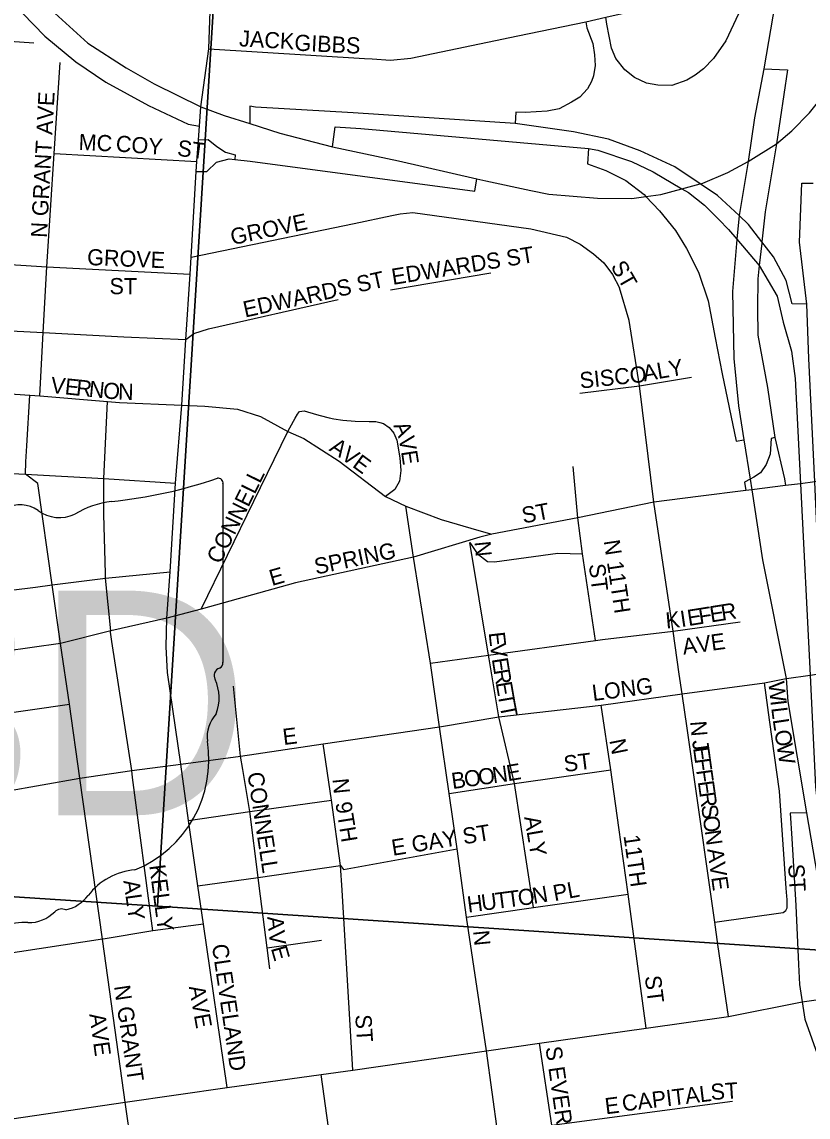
# Model space of a CAD drawing. Extents: x 0 to 34, y -6.2 to 22.
# Drawn here: x 7.114 to 7.576, y 18.119 to 18.762 of the extents above; entities that cross this region are included whole.
import ezdxf

# ---------------------------------------------------------------- set-up
doc = ezdxf.new("R2010")
doc.units = 0
for name, color, linetype in [('GM_X_City_Street', 7, 'Continuous'), ('GM_X_City_Street_Text', 7, 'Continuous'), ('GM_X_Interchange_Ramps', 7, 'Continuous'), ('GM_X_Interstate_Route', 7, 'Continuous'), ('GM_X_Section', 7, 'Continuous'), ('GM_X_State_Route', 7, 'Continuous'), ('GM_X_State_Shield', 7, 'Continuous'), ('GM_X_US_Route', 7, 'Continuous')]:
    doc.layers.add(name, color=color, linetype=linetype)

msp = doc.modelspace()

# ---------------------------------------------------------------- linework, layer by layer
at = {"layer": 'GM_X_City_Street'}
for points in [[(7.40517, 18.7533), (7.44499, 18.76153), (7.45674, 18.76428), (7.47785, 18.76892)], [(7.00564, 18.75627), (7.07288, 18.75262), (7.12097, 18.74924)], [(7.31508, 18.7401), (7.31966, 18.73982), (7.33048, 18.73914), (7.3424, 18.74032), (7.40517, 18.7533)], [(7.22375, 18.74564), (7.31508, 18.7401)], [(7.12443, 18.54206), (7.12656, 18.57921), (7.12864, 18.61789), (7.13299, 18.6844), (7.13639, 18.7378)], [(7.13299, 18.6844), (7.21671, 18.6797)], [(7.21331, 18.62353), (7.30909, 18.64316), (7.33113, 18.64792), (7.33606, 18.64893), (7.34356, 18.64973), (7.41273, 18.6401), (7.43371, 18.6352), (7.44184, 18.63115), (7.44953, 18.62554), (7.45555, 18.62008), (7.46072, 18.61323), (7.46492, 18.60552)], [(7.06414, 18.62187), (7.12864, 18.61789), (7.21273, 18.61353)], [(7.33044, 18.60435), (7.3892, 18.61425)], [(7.49995, 18.3788), (7.49637, 18.40414), (7.48497, 18.47979), (7.47654, 18.54796), (7.47052, 18.58635), (7.46492, 18.60552)], [(7.21027, 18.57512), (7.21498, 18.57874), (7.22358, 18.58147), (7.29973, 18.59872)], [(7.06178, 18.5827), (7.12656, 18.57921), (7.17383, 18.57683), (7.21027, 18.57512)], [(7.44154, 18.54379), (7.47654, 18.54796), (7.50705, 18.55304)], [(7.07551, 18.5454), (7.11865, 18.54255), (7.12443, 18.54206), (7.16429, 18.53873), (7.17125, 18.53815), (7.2078, 18.53656), (7.22144, 18.53599), (7.24054, 18.53434), (7.25401, 18.53006), (7.27006, 18.52113), (7.27946, 18.51702), (7.3002, 18.50376), (7.32739, 18.48315), (7.3394, 18.47731), (7.36009, 18.46962), (7.38216, 18.46319), (7.3898, 18.46097)], [(7.11688, 18.51286), (7.11865, 18.54255)], [(7.16307, 18.43797), (7.16211, 18.47254), (7.16216, 18.49368), (7.16429, 18.53873)], [(7.21924, 18.4169), (7.25019, 18.48025), (7.27006, 18.52113), (7.27345, 18.52733), (7.27434, 18.52897), (7.27585, 18.53145), (7.27703, 18.53288), (7.27968, 18.53336), (7.28699, 18.53111), (7.28908, 18.53056), (7.29447, 18.52914), (7.29711, 18.52873), (7.30237, 18.52792), (7.3097, 18.52719), (7.31792, 18.527), (7.32184, 18.52698), (7.32405, 18.52645), (7.32625, 18.52592), (7.32968, 18.52357), (7.33242, 18.52031), (7.33415, 18.51616), (7.3358, 18.5058), (7.33646, 18.49827), (7.33609, 18.49517), (7.33572, 18.49207), (7.33294, 18.48726), (7.32739, 18.48315)], [(7.17384, 18.13335), (7.16128, 18.22326), (7.1479, 18.31772), (7.14186, 18.36126), (7.13656, 18.39686), (7.13185, 18.43116), (7.1233, 18.49067), (7.11613, 18.49608), (7.11632, 18.50342), (7.11688, 18.51286)], [(6.99821, 18.50104), (7.02122, 18.50104), (7.05393, 18.49933), (7.07201, 18.49838), (7.11613, 18.49608), (7.16216, 18.49368), (7.20423, 18.49087)], [(7.45072, 18.39857), (7.4432, 18.4494), (7.44044, 18.47054), (7.43756, 18.50073)], [(7.58621, 18.49247), (7.57946, 18.49162), (7.57113, 18.49058), (7.56236, 18.48948), (7.54244, 18.48698), (7.5391, 18.48656), (7.51105, 18.48305)], [(7.56292, 18.37635), (7.57672, 18.37829), (7.58468, 18.37941), (7.591, 18.3803), (7.59427, 18.38091), (7.62982, 18.38756), (7.67292, 18.39175), (7.74898, 18.40202), (7.80065, 18.40857), (7.84375, 18.41455), (7.87636, 18.42025), (7.91447, 18.42624), (7.98084, 18.43482), (8.02749, 18.44183), (8.04476, 18.44573), (8.10377, 18.45197), (8.16636, 18.45877), (8.22058, 18.46707), (8.28899, 18.47797), (8.36777, 18.48959), (8.36789, 18.48961)], [(7.51105, 18.48305), (7.48497, 18.47979), (7.44044, 18.47054), (7.3898, 18.46097), (7.38277, 18.45921), (7.34384, 18.44752), (7.27462, 18.43245), (7.21924, 18.4169), (7.19917, 18.41171)], [(7.46619, 17.59955), (7.45992, 17.64528), (7.4533, 17.69188), (7.44628, 17.73938), (7.43896, 17.7841), (7.43222, 17.83028), (7.42585, 17.87679), (7.41935, 17.92213), (7.40765, 18.01027), (7.39992, 18.06535), (7.39349, 18.10929), (7.38667, 18.15777), (7.37502, 18.23626), (7.36962, 18.27633), (7.36489, 18.30872), (7.35913, 18.34789), (7.35379, 18.38527), (7.34384, 18.44752), (7.3394, 18.47731)], [(7.37691, 18.45609), (7.38136, 18.44963), (7.38739, 18.44501), (7.39148, 18.44477), (7.42862, 18.44982), (7.4432, 18.4494)], [(7.38829, 18.38784), (7.38794, 18.38997), (7.37691, 18.45609)], [(7.1219, 18.42992), (7.13185, 18.43116), (7.16316, 18.43509), (7.20094, 18.43887)], [(7.16677, 18.39793), (7.16591, 18.40351), (7.16624, 18.40427), (7.16316, 18.43509), (7.16315, 18.43526), (7.16307, 18.43797)], [(6.99364, 18.4138), (6.99621, 18.4142), (7.06306, 18.42262), (7.1219, 18.42992)], [(7.45478, 18.39906), (7.49637, 18.40414), (7.53564, 18.40952)], [(7.17899, 18.3182), (7.17844, 18.32236), (7.16677, 18.39793)], [(7.35379, 18.38527), (7.38794, 18.38997), (7.45072, 18.39857), (7.45478, 18.39906)], [(7.41428, 18.24196), (7.40328, 18.31461), (7.39396, 18.35384), (7.38829, 18.38784)], [(7.50451, 18.3471), (7.50159, 18.36721), (7.49995, 18.3788)], [(7.20735, 18.32594), (7.24241, 18.33063), (7.29087, 18.33792), (7.35913, 18.34789), (7.39396, 18.35384), (7.45399, 18.36071), (7.50159, 18.36721), (7.54993, 18.37366), (7.5627, 18.37632), (7.56292, 18.37635)], [(7.52072, 18.23328), (7.56094, 18.23893), (7.56246, 18.24008), (7.56324, 18.24181), (7.56322, 18.24662), (7.56307, 18.24858), (7.56271, 18.2533), (7.55873, 18.31012), (7.553, 18.35198), (7.54993, 18.37366)], [(7.24372, 18.32286), (7.24241, 18.33063), (7.23818, 18.37171)], [(6.93928, 18.33213), (7.00978, 18.34232), (7.07511, 18.35167), (7.14186, 18.36126)], [(7.4804, 18.17115), (7.46996, 18.24982), (7.46444, 18.28884), (7.45966, 18.32264), (7.45399, 18.36071)], [(7.52261, 18.22029), (7.52072, 18.23328), (7.50809, 18.32249), (7.50451, 18.3471)], [(7.30197, 18.25211), (7.3011, 18.26656), (7.29572, 18.30482), (7.29087, 18.33792)], [(7.23446, 18.13639), (7.22051, 18.23222), (7.21733, 18.25463), (7.2117, 18.29296), (7.20735, 18.32594)], [(7.25336, 18.25471), (7.25275, 18.2595), (7.24788, 18.29823), (7.24372, 18.32286)], [(7.36489, 18.30872), (7.40328, 18.31461), (7.45966, 18.32264)], [(7.19095, 18.22825), (7.17899, 18.3182)], [(7.2117, 18.29296), (7.24788, 18.29823), (7.29572, 18.30482)], [(7.21733, 18.25463), (7.25275, 18.2595), (7.3011, 18.26656), (7.30272, 18.26424), (7.36962, 18.27633)], [(7.25955, 18.20592), (7.25805, 18.21817), (7.25336, 18.25471)], [(7.30833, 18.14648), (7.30197, 18.25211)], [(7.37502, 18.23626), (7.41428, 18.24196), (7.46996, 18.24982)], [(7.22051, 18.23222), (7.19095, 18.22825), (7.16179, 18.22335)], [(7.16179, 18.22335), (7.16128, 18.22326), (7.10093, 18.2142), (7.0431, 18.2053), (6.98365, 18.19789), (6.93221, 18.19042), (6.88585, 18.18367), (6.83933, 18.1771), (6.79329, 18.17102), (6.70008, 18.1572), (6.65161, 18.15162), (6.60426, 18.14435), (6.55749, 18.13701), (6.51159, 18.13017), (6.46597, 18.12433)], [(7.25805, 18.21817), (7.28989, 18.2227)], [(7.52875, 18.17804), (7.52261, 18.22029)], [(7.42686, 18.10338), (7.42506, 18.11427), (7.41779, 18.16222)], [(7.3054, 18.02637), (7.30213, 18.0516), (7.29657, 18.09449), (7.2896, 18.14393)], [(7.23322, 17.71125), (7.22675, 17.75285), (7.21943, 17.80001), (7.21457, 17.84757), (7.20786, 17.89233), (7.20148, 17.93834), (7.19504, 17.98459), (7.18784, 18.03558), (7.18208, 18.076), (7.17463, 18.12771), (7.17384, 18.13335)], [(7.39349, 18.10929), (7.42506, 18.11427), (7.53117, 18.12832)]]:
    msp.add_lwpolyline(points, dxfattribs=at)
at = {"layer": 'GM_X_Interchange_Ramps'}
for points in [[(7.57798, 18.94501), (7.57472, 18.88766), (7.56734, 18.81732), (7.55628, 18.77296), (7.54952, 18.73402), (7.54416, 18.70523), (7.54045, 18.67958), (7.53502, 18.64789), (7.53372, 18.63401), (7.53371, 18.63391), (7.53115, 18.60338), (7.5319, 18.56409), (7.53464, 18.53619), (7.53785, 18.51634), (7.54148, 18.49317), (7.54244, 18.48698), (7.54886, 18.44591), (7.5627, 18.37632), (7.56362, 18.36275), (7.5747, 18.29736), (7.58088, 18.26084)], [(7.09428, 18.814), (7.08391, 18.80494), (7.09639, 18.78733), (7.10791, 18.77326), (7.12743, 18.7531), (7.14566, 18.73806), (7.16327, 18.72622), (7.18823, 18.71246), (7.21159, 18.70158), (7.21818, 18.70031)], [(7.53462, 18.76636), (7.52719, 18.75038), (7.52006, 18.74006), (7.51413, 18.73396), (7.50936, 18.73025), (7.50446, 18.72743), (7.49556, 18.7242), (7.48738, 18.72446), (7.48065, 18.72554), (7.47371, 18.72891), (7.46793, 18.73342), (7.46272, 18.74006), (7.46011, 18.74618), (7.45737, 18.76012), (7.45674, 18.76428)], [(7.44499, 18.76153), (7.44557, 18.75799), (7.4492, 18.74883), (7.45013, 18.74225), (7.45053, 18.7359), (7.44964, 18.72981), (7.44846, 18.72653), (7.44597, 18.72217), (7.44147, 18.71747), (7.43672, 18.71435), (7.42943, 18.71062), (7.42231, 18.70915), (7.4094, 18.7083), (7.40391, 18.70856), (7.40353, 18.70192)], [(7.54952, 18.73402), (7.5634, 18.73346), (7.55692, 18.69006), (7.55038, 18.65008), (7.54844, 18.63252), (7.54833, 18.63161), (7.54689, 18.61861), (7.54603, 18.61083), (7.54577, 18.59364), (7.54615, 18.57773), (7.55179, 18.54695), (7.55613, 18.51763), (7.56172, 18.49336), (7.56236, 18.48948)], [(7.57478, 18.59587), (7.56628, 18.59605), (7.5627, 18.6098), (7.55526, 18.62365), (7.54844, 18.63252), (7.54066, 18.64262), (7.53502, 18.64789), (7.52243, 18.65966), (7.51229, 18.66651), (7.49742, 18.67656), (7.47693, 18.68582), (7.45842, 18.69269), (7.43783, 18.69694), (7.40353, 18.70192), (7.30857, 18.70827), (7.25117, 18.71142), (7.24781, 18.71206), (7.24771, 18.70193)], [(7.29628, 18.68816), (7.29785, 18.69991), (7.31292, 18.69893), (7.44669, 18.68731), (7.45215, 18.68628), (7.47185, 18.67962), (7.48462, 18.67357), (7.50149, 18.66364), (7.50539, 18.66135), (7.51472, 18.65395), (7.52307, 18.64566), (7.52874, 18.63981), (7.53372, 18.63401), (7.54689, 18.61861), (7.55731, 18.60056), (7.56096, 18.58538), (7.56579, 18.56833), (7.56806, 18.55226), (7.57113, 18.49058), (7.57672, 18.37829), (7.57998, 18.31264), (7.58561, 18.26074), (7.58088, 18.26084)], [(7.21761, 18.69243), (7.22342, 18.69246), (7.22838, 18.68846), (7.2335, 18.6851), (7.2391, 18.6835), (7.23894, 18.68076)], [(7.44669, 18.68731), (7.44607, 18.67833), (7.45687, 18.67433), (7.46855, 18.66838), (7.47924, 18.66028), (7.48031, 18.65914), (7.48831, 18.6506), (7.49773, 18.63922), (7.50415, 18.62864), (7.51125, 18.61466), (7.5168, 18.59788), (7.52105, 18.57621), (7.52502, 18.55503), (7.5334, 18.51562), (7.53785, 18.51634)], [(7.21635, 18.67374), (7.22247, 18.67374), (7.22823, 18.67918), (7.23558, 18.68111), (7.23894, 18.68076), (7.24806, 18.67983), (7.3799, 18.66222), (7.38113, 18.66939)], [(7.59642, 18.31642), (7.58766, 18.31537), (7.58468, 18.37941), (7.57946, 18.49162), (7.57608, 18.56406), (7.57478, 18.59587), (7.57059, 18.63234), (7.57179, 18.66699), (7.57845, 18.66684)], [(7.55613, 18.51763), (7.55398, 18.51713), (7.5532, 18.50793), (7.5509, 18.50185), (7.54762, 18.49694), (7.5438, 18.49445), (7.54148, 18.49317), (7.5383, 18.49143), (7.5391, 18.48656)], [(7.5747, 18.29736), (7.56505, 18.29725), (7.56596, 18.28238), (7.56844, 18.24303), (7.56987, 18.20848), (7.57059, 18.19665), (7.57204, 18.18651)], [(7.57204, 18.18651), (7.57366, 18.17641), (7.58904, 18.13296), (7.59445, 18.11639), (7.6002, 18.09595), (7.60108, 18.09284), (7.60926, 18.0933)]]:
    msp.add_lwpolyline(points, dxfattribs=at)
at = {"layer": 'GM_X_Interstate_Route'}
for points in [[(7.10052, 18.80588), (7.11435, 18.78791), (7.12902, 18.77063), (7.15269, 18.74908), (7.17518, 18.73464), (7.19169, 18.72517), (7.21899, 18.71164)], [(7.41279, 18.6626), (7.42326, 18.66039), (7.45184, 18.65803), (7.47202, 18.658), (7.48031, 18.65914), (7.48913, 18.66035), (7.50149, 18.66364), (7.51229, 18.66651), (7.5137, 18.66689), (7.52847, 18.67326), (7.54045, 18.67958), (7.55692, 18.69006), (7.56594, 18.6976), (7.57641, 18.70824), (7.59483, 18.7311), (7.59928, 18.73976)], [(7.21899, 18.71164), (7.23266, 18.70664), (7.24771, 18.70193)], [(7.24771, 18.70193), (7.26546, 18.69617), (7.29628, 18.68816), (7.33503, 18.67996), (7.38113, 18.66939), (7.38641, 18.66819), (7.41279, 18.6626)]]:
    msp.add_lwpolyline(points, dxfattribs=at)
at = {"layer": 'GM_X_Section'}
for points in [[(6.76078, 19.26937), (7.25546, 19.23647), (7.19351, 18.24276), (6.6863, 18.2758)], [(7.25546, 19.23647), (7.74778, 19.20365), (7.67976, 18.21035), (7.19351, 18.24276)], [(6.68124, 18.27598), (6.6863, 18.2758), (7.19351, 18.24276), (7.67976, 18.21035), (7.62278, 17.23025), (6.6036, 17.30139)]]:
    msp.add_lwpolyline(points, close=True, dxfattribs=at)
at = {"layer": 'GM_X_State_Route'}
for points in [[(7.22375, 18.74564), (7.23046, 18.93234), (7.24216, 19.11376)], [(7.21858, 18.70598), (7.21899, 18.71164), (7.22375, 18.74564)], [(7.19917, 18.41171), (7.20094, 18.43887), (7.20423, 18.49087), (7.2078, 18.53656), (7.21027, 18.57512), (7.21273, 18.61353), (7.21331, 18.62353), (7.21635, 18.67374), (7.21671, 18.6797), (7.21705, 18.68455), (7.21761, 18.69243), (7.21818, 18.70031), (7.21858, 18.70598)], [(7.19917, 18.41171), (7.16624, 18.40427), (7.13656, 18.39686), (7.06996, 18.38741), (7.00502, 18.37939), (6.9337, 18.36781), (6.89786, 18.36304), (6.85988, 18.36813)], [(7.20735, 18.32594), (7.20735, 18.32594), (7.1994, 18.37982), (7.19862, 18.39483), (7.19917, 18.41171)], [(6.87286, 18.2759), (6.91035, 18.28117), (6.91873, 18.28248), (6.94619, 18.28626), (6.97138, 18.29097), (7.01607, 18.2966), (7.02924, 18.29838), (7.08144, 18.30603), (7.1479, 18.31772), (7.17844, 18.32236), (7.20735, 18.32594)]]:
    msp.add_lwpolyline(points, dxfattribs=at)
at = {"layer": 'GM_X_State_Shield'}
for p, q in [((7.23207, 18.38576), (7.23207, 18.49045)), ((7.23204, 18.38579), (7.23207, 18.38576))]:
    msp.add_line(p, q, dxfattribs=at)
for centre, radius, start, end in [((7.13815, 18.75832), 0.27962, 275.84447, 288.90645), ((7.22914, 18.49088), 0.00294, 351.86209, 97.738), ((7.11312, 18.46038), 0.01777, 54.46668, 119.14113), ((7.17381, 18.42436), 0.05625, 97.34618, 120.76885), ((7.13606, 18.4921), 0.02138, 233.85621, 294.82819), ((7.22894, 18.38536), 0.00314, 289.60381, 7.73413), ((7.23139, 18.37808), 0.00454, 107.94398, 210.33697), ((7.20249, 18.36484), 0.02727, 340.03296, 23.64957), ((7.24258, 18.34195), 0.01984, 136.8065, 186.92959), ((7.15381, 18.32863), 0.06994, 292.30889, 8.98584), ((7.1833, 18.22574), 0.0383, 94.40312, 142.57675), ((7.13477, 18.26253), 0.0226, 282.87319, 323.27711), ((7.11801, 18.2544), 0.02136, 268.77702, 315.54927), ((7.13733, 18.23502), 0.00601, 65.75173, 132.64842), ((7.11508, 18.2002), 0.03294, 85.69512, 111.20995)]:
    msp.add_arc(centre, radius, start, end, dxfattribs=at)
at = {"layer": 'GM_X_US_Route'}
for points in [[(7.23446, 18.13639), (7.2896, 18.14393), (7.30833, 18.14648), (7.38667, 18.15777), (7.41779, 18.16222), (7.4804, 18.17115), (7.52875, 18.17804), (7.57204, 18.18651), (7.58167, 18.18788)], [(6.9976, 18.10156), (6.99959, 18.10185), (7.08788, 18.11499), (7.17463, 18.12771), (7.23446, 18.13639)]]:
    msp.add_lwpolyline(points, dxfattribs=at)

# ---------------------------------------------------------------- texts
at = {"layer": 'GM_X_City_Street_Text'}
for s, height, rotation, p in [('JACK', 0.00947, 356.73129, (7.24134, 18.74723)), ('GIBBS', 0.00947, 357.20885, (7.27382, 18.74473)), ('N GRANT AVE', 0.0094697, 86.92619, (7.12863, 18.63469)), ('MC', 0.00947, 357.39924, (7.14715, 18.6864)), ('COY', 0.00947, 355.5983, (7.16887, 18.68556)), ('ST', 0.00947, 352.41108, (7.20481, 18.68305)), ('GROVE', 0.00947, 12.01375, (7.23753, 18.63053)), ('EDWARDS ST', 0.00947, 9.14141, (7.33179, 18.60721)), ('GROVE', 0.00947, 357.61538, (7.15214, 18.6189)), ('ST', 0.00947, 299.74489, (7.4594, 18.61808)), ('ST', 0.00947, 0.00001, (7.16541, 18.60177)), ('EDWARDS ST', 0.00947, 12.45856, (7.24502, 18.58802)), ('SISCO', 0.00947, 5.8526, (7.44189, 18.54639)), ('ALY', 0.00947, 9.78468, (7.47927, 18.55054)), ('V', 0.00947, 354.21981, (7.13059, 18.54389)), ('E', 0.00947, 354.19696, (7.13888, 18.54305)), ('R', 0.00947, 354.21895, (7.14551, 18.54237)), ('N', 0.00947, 354.19806, (7.15297, 18.54162)), ('O', 0.00947, 354.64318, (7.16134, 18.54077)), ('N', 0.00947, 358.56278, (7.17035, 18.53995)), ('A', 0.00947, 292.82836, (7.33193, 18.52472)), ('A', 0.00947, 325.94624, (7.29388, 18.51027)), ('V', 0.00947, 280.75261, (7.33501, 18.51755)), ('V', 0.00947, 324.32769, (7.30073, 18.50565)), ('E', 0.00947, 323.74764, (7.30748, 18.5008)), ('E', 0.00947, 278.66723, (7.33655, 18.50945)), ('CONNELL', 0.00947, 63.8245, (7.23047, 18.4429)), ('ST', 0.00947, 10.61471, (7.40841, 18.4672)), ('SPRING', 0.00947, 11.76629, (7.28671, 18.43719)), ('N', 0.00947, 275.73008, (7.37967, 18.45646)), ('N 11TH', 0.00947, 278.65224, (7.45553, 18.45701)), ('ST', 0.00947, 277.13512, (7.44682, 18.44312)), ('E', 0.00947, 15.93715, (7.26075, 18.43049)), ('E', 0.00947, 9.04454, (7.50538, 18.40703)), ('F', 0.00947, 9.05359, (7.51197, 18.40808)), ('E', 0.00947, 9.0266, (7.51855, 18.40913)), ('R', 0.00947, 9.04291, (7.52514, 18.41018)), ('K', 0.00947, 5.2538, (7.4923, 18.40557)), ('I', 0.00947, 8.51183, (7.50117, 18.4064)), ('E', 0.00947, 276.40658, (7.38801, 18.40314)), ('AVE', 0.00947, 7.85663, (7.50239, 18.39024)), ('V', 0.00947, 276.88078, (7.38876, 18.39643)), ('E', 0.00947, 279.08357, (7.38982, 18.38777)), ('R', 0.00947, 279.71229, (7.39088, 18.38108)), ('E', 0.00947, 279.7448, (7.39215, 18.37369)), ('LONG', 0.00947, 7.30774, (7.44935, 18.36305)), ('W', 0.00947, 276.62242, (7.55217, 18.37399)), ('T', 0.00947, 279.74528, (7.39328, 18.36712)), ('T', 0.00947, 281.03295, (7.39445, 18.36032)), ('I', 0.00947, 276.61536, (7.55342, 18.36323)), ('L', 0.00947, 276.99761, (7.55391, 18.35902)), ('E', 0.00947, 7.11829, (7.26768, 18.33722)), ('N', 0.00947, 274.61663, (7.50636, 18.35108)), ('L', 0.00947, 278.46468, (7.55476, 18.35214)), ('N', 0.00947, 281.30574, (7.45882, 18.33996)), ('O', 0.00947, 278.85551, (7.55575, 18.34547)), ('J', 0.00947, 277.81383, (7.50742, 18.33972)), ('E', 0.00947, 278.00012, (7.50799, 18.33556)), ('W', 0.00947, 278.88435, (7.55703, 18.33724)), ('ST', 0.00947, 7.12165, (7.43268, 18.32139)), ('F', 0.00947, 277.97557, (7.50892, 18.32896)), ('CONNELL', 0.00947, 278.75098, (7.24633, 18.3207)), ('B', 0.00947, 8.01675, (7.36683, 18.31138)), ('O', 0.00947, 8.00338, (7.37426, 18.31243)), ('O', 0.00947, 8.02082, (7.38251, 18.31359)), ('N', 0.00947, 8.00338, (7.39076, 18.31475)), ('E', 0.00947, 9.38051, (7.39926, 18.31595)), ('F', 0.00947, 278.00012, (7.50984, 18.32235)), ('N', 0.00947, 275.70844, (7.29634, 18.31729)), ('E', 0.00947, 278.00262, (7.51077, 18.31575)), ('R', 0.00947, 277.99271, (7.5117, 18.30915)), ('9TH', 0.00947, 279.09335, (7.298, 18.30323)), ('S', 0.00947, 277.97557, (7.51274, 18.30172)), ('O', 0.00947, 277.98174, (7.51367, 18.29512)), ('E GAY ST', 0.00947, 9.16423, (7.33178, 18.27221)), ('ALY', 0.00947, 279.78468, (7.40882, 18.29492)), ('11TH', 0.00947, 278.13084, (7.46716, 18.28404)), ('N', 0.00947, 277.99864, (7.51483, 18.28686)), ('A', 0.00947, 277.99864, (7.51633, 18.27613)), ('KELLY', 0.00947, 277.59497, (7.18872, 18.2665)), ('V', 0.00947, 277.98174, (7.51749, 18.26788)), ('ST', 0.00947, 273.36421, (7.56385, 18.26722)), ('ALY', 0.00947, 278.12574, (7.17354, 18.25756)), ('PL', 0.00947, 10.61471, (7.42674, 18.24554)), ('E', 0.00947, 278.00012, (7.51865, 18.25962)), ('U', 0.00947, 7.45082, (7.38427, 18.23997)), ('T', 0.00947, 7.42316, (7.39253, 18.24105)), ('T', 0.00947, 7.47386, (7.39915, 18.24191)), ('O', 0.00947, 7.80431, (7.40582, 18.24279)), ('N', 0.00947, 9.83129, (7.41444, 18.24397)), ('H', 0.00947, 7.45308, (7.37601, 18.23889)), ('A', 0.00947, 275.40615, (7.25801, 18.23643)), ('V', 0.00947, 276.48279, (7.25882, 18.22794)), ('N', 0.00947, 275.70628, (7.37884, 18.22813)), ('CLEVELAND', 0.00947, 278.32407, (7.2255, 18.21987)), ('E', 0.00947, 286.03197, (7.26009, 18.21797)), ('ST', 0.00947, 277.12166, (7.47967, 18.2015)), ('N GRANT', 0.00947, 278.3923, (7.168, 18.19571)), ('AVE', 0.00947, 280.12684, (7.21195, 18.1954)), ('AVE', 0.00947, 277.85664, (7.15353, 18.1793)), ('ST', 0.00947, 273.57465, (7.30968, 18.17889)), ('S EVERETT ALY', 0.0094697, 278.13011, (7.42134, 18.15981)), ('CAPITAL', 0.00947, 6.76636, (7.46686, 18.12222)), ('ST', 0.00947, 3.81214, (7.51862, 18.1289)), ('E', 0.00947, 7.12165, (7.45685, 18.12055))]:
    msp.add_text(s, height=height, rotation=rotation, dxfattribs=at).set_placement(p)
at = {"layer": 'GM_X_State_Shield'}
msp.add_text('3D', height=0.131836, dxfattribs=at).set_placement((7.0228, 18.29603))

doc.saveas('drawing.dxf')
